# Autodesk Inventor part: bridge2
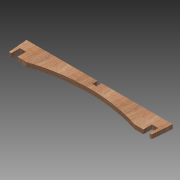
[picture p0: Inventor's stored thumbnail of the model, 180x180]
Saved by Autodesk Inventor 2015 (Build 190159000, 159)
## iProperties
Created: 2015-04
Part Number: bridge2
Material: Wood (Birch)
Document SubType Name: Modeling
Designer: sungeun
Density: 0.55 g/cm^3
Appearance: Birch - Natural Polished
Author: sungeun
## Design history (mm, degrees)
sketch "Sketch1"
  geometry: L1 (-410.376, 0)-(-420, 110); L2 (-420, 110)-(0, 110); L3 (-410.376, 0)-(-310.376, 0); L4 (0, 110)-(0, 120); L5 (420, 110)-(0, 110); L6 (410.376, 0)-(420, 110); L7 (410.376, 0)-(310.376, 0); A1 r 1000 centre (0, -950.614) between (310.376, 0) and (-310.376, 0); 1 further point
  constraints: 14 end point, 3 symmetric about line, 2 horizontal, 2 point on circle, 1 centre point, 1 horizontal alignment, 1 vertical, 1 vertical alignment
  dimensions: "height" = 110 distance from line of point (0, 0) L2; "d2" = 85 deg angle of L2 L1; "d3" = 100 distance of L1.start L3.end; "d8" = 420 distance of L1.end L2.end; "d19" = 1000 radius of A1
extrude "Extrusion1" new body sketch "Sketch1" distance "d6" = 24 (= 2 x thickness); taper "d7" = 0 deg
sketch "Sketch2"
  geometry: L1 (-397.746, 50)-(-361.746, 50); L2 (-361.746, 50)-(-361.746, -10); L3 (-361.746, -10)-(-397.746, -10); L4 (-397.746, -10)-(-397.746, 50); L5 (-410.376, 0)-(-310.376, 0) reference; L6 (420, 110)-(-420, 110) reference; L7 (0, 110)-(0, 0); L8 (397.746, 50)-(361.746, 50); L9 (361.746, 50)-(361.746, -10); L10 (397.746, -10)-(397.746, 50); L11 (361.746, -10)-(397.746, -10); 2 further points
  constraints: 18 end point, 4 symmetric about line, 3 midpoint, 2 parallel, 1 horizontal, 1 perpendicular, 1 vertical
  dimensions: "d10" = 60 distance between parallel lines of L3 L1; "d11" = 36 distance of L1.start L1.end (= 3 x thickness); "d12" = 60 distance between parallel lines of L6 L1; "d20" = 379.8775 distance of L7.end point (-379.746, -10)
extrude "Extrusion2" cut sketch "Sketch2" stored distance "d13" = 10; taper "d14" = 0 deg
sketch "Sketch3"
  geometry: L1 (420, 110)-(-420, 110) reference; L2 (-12, 110)-(12, 110); L3 (12, 110)-(12, 80); L4 (12, 80)-(-12, 80); L5 (-12, 80)-(-12, 110); 2 further points
  constraints: 8 end point, 2 parallel, 1 horizontal, 1 midpoint, 1 perpendicular, 1 point on line, 1 vertical alignment
  dimensions: "d15" = 30 distance of L2.end L3.end; "d16" = 24 distance of L3.end L4.end (= 2 x thickness)
extrude "Extrusion3" cut sketch "Sketch3" stored distance "d17" = 10; taper "d18" = 0 deg
body "Solid1"
other parameters: "thickness" = 12 [user parameter; used in 3 equation terms]
